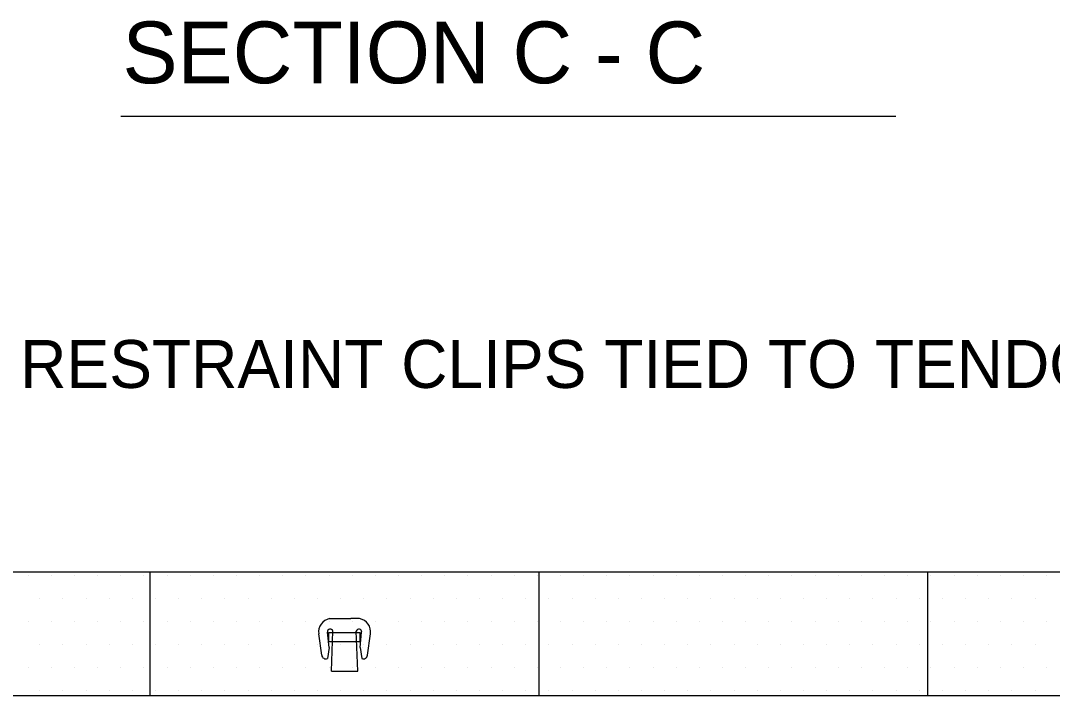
# Model space of a CAD drawing. Extents: x 638850 to 644908, y 297188 to 298900.
# Drawn here: x 641716.6 to 641776.8, y 297411.7 to 297451.1 of the extents above; entities that cross this region are included whole.
import ezdxf

# ---------------------------------------------------------------- set-up
doc = ezdxf.new("R2010")
doc.units = 0
for name, color, linetype in [('12', 7, 'Continuous'), ('3', 7, 'Continuous'), ('5', 7, 'Continuous'), ('7', 7, 'Continuous')]:
    doc.layers.add(name, color=color, linetype=linetype)

msp = doc.modelspace()

# ---------------------------------------------------------------- linework, layer by layer
at = {"layer": '12'}
for p, q in [((641717.032, 297418.735), (641717.032, 297418.735)), ((641718.382, 297418.735), (641718.382, 297418.735)), ((641719.732, 297418.735), (641719.732, 297418.735)), ((641721.082, 297418.735), (641721.082, 297418.735)), ((641722.432, 297418.735), (641722.432, 297418.735)), ((641723.782, 297418.735), (641723.782, 297418.735)), ((641725.132, 297418.735), (641725.132, 297418.735)), ((641726.482, 297418.735), (641726.482, 297418.735)), ((641727.832, 297418.735), (641727.832, 297418.735)), ((641729.182, 297418.735), (641729.182, 297418.735)), ((641730.532, 297418.735), (641730.532, 297418.735)), ((641731.882, 297418.735), (641731.882, 297418.735)), ((641733.232, 297418.735), (641733.232, 297418.735)), ((641734.582, 297418.735), (641734.582, 297418.735)), ((641735.932, 297418.735), (641735.932, 297418.735)), ((641737.282, 297418.735), (641737.282, 297418.735)), ((641738.632, 297418.735), (641738.632, 297418.735)), ((641739.982, 297418.735), (641739.982, 297418.735)), ((641741.332, 297418.735), (641741.332, 297418.735)), ((641742.682, 297418.735), (641742.682, 297418.735)), ((641744.032, 297418.735), (641744.032, 297418.735)), ((641745.382, 297418.735), (641745.382, 297418.735)), ((641746.732, 297418.735), (641746.732, 297418.735)), ((641748.082, 297418.735), (641748.082, 297418.735)), ((641749.432, 297418.735), (641749.432, 297418.735)), ((641750.782, 297418.735), (641750.782, 297418.735)), ((641752.132, 297418.735), (641752.132, 297418.735)), ((641753.482, 297418.735), (641753.482, 297418.735)), ((641754.832, 297418.735), (641754.832, 297418.735)), ((641756.182, 297418.735), (641756.182, 297418.735)), ((641757.532, 297418.735), (641757.532, 297418.735)), ((641758.882, 297418.735), (641758.882, 297418.735)), ((641760.232, 297418.735), (641760.232, 297418.735)), ((641761.582, 297418.735), (641761.582, 297418.735)), ((641762.932, 297418.735), (641762.932, 297418.735)), ((641764.282, 297418.735), (641764.282, 297418.735)), ((641765.632, 297418.735), (641765.632, 297418.735)), ((641766.982, 297418.735), (641766.982, 297418.735)), ((641768.332, 297418.735), (641768.332, 297418.735)), ((641769.682, 297418.735), (641769.682, 297418.735)), ((641771.032, 297418.735), (641771.032, 297418.735)), ((641772.382, 297418.735), (641772.382, 297418.735)), ((641773.732, 297418.735), (641773.732, 297418.735)), ((641775.082, 297418.735), (641775.082, 297418.735)), ((641776.432, 297418.735), (641776.432, 297418.735)), ((641717.706, 297417.385), (641717.706, 297417.385)), ((641719.058, 297417.385), (641719.058, 297417.385)), ((641720.406, 297417.385), (641720.406, 297417.385)), ((641721.758, 297417.385), (641721.758, 297417.385)), ((641723.106, 297417.385), (641723.106, 297417.385)), ((641724.458, 297417.385), (641724.458, 297417.385)), ((641725.806, 297417.385), (641725.806, 297417.385)), ((641727.158, 297417.385), (641727.158, 297417.385)), ((641728.506, 297417.385), (641728.506, 297417.385)), ((641729.858, 297417.385), (641729.858, 297417.385)), ((641731.206, 297417.385), (641731.206, 297417.385)), ((641732.558, 297417.385), (641732.558, 297417.385)), ((641733.906, 297417.385), (641733.906, 297417.385)), ((641735.258, 297417.385), (641735.258, 297417.385)), ((641736.606, 297417.385), (641736.606, 297417.385)), ((641737.958, 297417.385), (641737.958, 297417.385)), ((641739.306, 297417.385), (641739.306, 297417.385)), ((641740.658, 297417.385), (641740.658, 297417.385)), ((641742.006, 297417.385), (641742.006, 297417.385)), ((641743.358, 297417.385), (641743.358, 297417.385)), ((641744.706, 297417.385), (641744.706, 297417.385)), ((641746.058, 297417.385), (641746.058, 297417.385)), ((641747.406, 297417.385), (641747.406, 297417.385)), ((641748.758, 297417.385), (641748.758, 297417.385)), ((641750.106, 297417.385), (641750.106, 297417.385)), ((641751.458, 297417.385), (641751.458, 297417.385)), ((641752.806, 297417.385), (641752.806, 297417.385)), ((641754.158, 297417.385), (641754.158, 297417.385)), ((641755.506, 297417.385), (641755.506, 297417.385)), ((641756.858, 297417.385), (641756.858, 297417.385)), ((641758.206, 297417.385), (641758.206, 297417.385)), ((641759.558, 297417.385), (641759.558, 297417.385)), ((641760.906, 297417.385), (641760.906, 297417.385)), ((641762.258, 297417.385), (641762.258, 297417.385)), ((641763.606, 297417.385), (641763.606, 297417.385)), ((641764.958, 297417.385), (641764.958, 297417.385)), ((641766.306, 297417.385), (641766.306, 297417.385)), ((641767.658, 297417.385), (641767.658, 297417.385)), ((641769.006, 297417.385), (641769.006, 297417.385)), ((641770.358, 297417.385), (641770.358, 297417.385)), ((641771.706, 297417.385), (641771.706, 297417.385)), ((641773.058, 297417.385), (641773.058, 297417.385)), ((641774.406, 297417.385), (641774.406, 297417.385)), ((641775.758, 297417.385), (641775.758, 297417.385)), ((641717.032, 297416.035), (641717.032, 297416.035)), ((641718.382, 297416.035), (641718.382, 297416.035)), ((641719.732, 297416.035), (641719.732, 297416.035)), ((641721.082, 297416.035), (641721.082, 297416.035)), ((641722.432, 297416.035), (641722.432, 297416.035)), ((641723.782, 297416.035), (641723.782, 297416.035)), ((641725.132, 297416.035), (641725.132, 297416.035)), ((641726.482, 297416.035), (641726.482, 297416.035)), ((641727.832, 297416.035), (641727.832, 297416.035)), ((641729.182, 297416.035), (641729.182, 297416.035)), ((641730.532, 297416.035), (641730.532, 297416.035)), ((641731.882, 297416.035), (641731.882, 297416.035)), ((641733.232, 297416.035), (641733.232, 297416.035)), ((641734.582, 297416.035), (641734.582, 297416.035)), ((641735.932, 297416.035), (641735.932, 297416.035)), ((641737.282, 297416.035), (641737.282, 297416.035)), ((641738.632, 297416.035), (641738.632, 297416.035)), ((641739.982, 297416.035), (641739.982, 297416.035)), ((641741.332, 297416.035), (641741.332, 297416.035)), ((641742.682, 297416.035), (641742.682, 297416.035)), ((641744.032, 297416.035), (641744.032, 297416.035)), ((641745.382, 297416.035), (641745.382, 297416.035)), ((641746.732, 297416.035), (641746.732, 297416.035)), ((641748.082, 297416.035), (641748.082, 297416.035)), ((641749.432, 297416.035), (641749.432, 297416.035)), ((641750.782, 297416.035), (641750.782, 297416.035)), ((641752.132, 297416.035), (641752.132, 297416.035)), ((641753.482, 297416.035), (641753.482, 297416.035)), ((641754.832, 297416.035), (641754.832, 297416.035)), ((641756.182, 297416.035), (641756.182, 297416.035)), ((641757.532, 297416.035), (641757.532, 297416.035)), ((641758.882, 297416.035), (641758.882, 297416.035)), ((641760.232, 297416.035), (641760.232, 297416.035)), ((641761.582, 297416.035), (641761.582, 297416.035)), ((641762.932, 297416.035), (641762.932, 297416.035)), ((641764.282, 297416.035), (641764.282, 297416.035)), ((641765.632, 297416.035), (641765.632, 297416.035)), ((641766.982, 297416.035), (641766.982, 297416.035)), ((641768.332, 297416.035), (641768.332, 297416.035)), ((641769.682, 297416.035), (641769.682, 297416.035)), ((641771.032, 297416.035), (641771.032, 297416.035)), ((641772.382, 297416.035), (641772.382, 297416.035)), ((641773.732, 297416.035), (641773.732, 297416.035)), ((641775.082, 297416.035), (641775.082, 297416.035)), ((641776.432, 297416.035), (641776.432, 297416.035)), ((641717.706, 297414.685), (641717.706, 297414.685)), ((641719.058, 297414.685), (641719.058, 297414.685)), ((641720.406, 297414.685), (641720.406, 297414.685)), ((641721.758, 297414.685), (641721.758, 297414.685)), ((641723.106, 297414.685), (641723.106, 297414.685)), ((641724.458, 297414.685), (641724.458, 297414.685)), ((641725.806, 297414.685), (641725.806, 297414.685)), ((641727.158, 297414.685), (641727.158, 297414.685)), ((641728.506, 297414.685), (641728.506, 297414.685)), ((641729.858, 297414.685), (641729.858, 297414.685)), ((641731.206, 297414.685), (641731.206, 297414.685)), ((641732.558, 297414.685), (641732.558, 297414.685)), ((641733.906, 297414.685), (641733.906, 297414.685)), ((641735.258, 297414.685), (641735.258, 297414.685)), ((641736.606, 297414.685), (641736.606, 297414.685)), ((641737.958, 297414.685), (641737.958, 297414.685)), ((641739.306, 297414.685), (641739.306, 297414.685)), ((641740.658, 297414.685), (641740.658, 297414.685)), ((641742.006, 297414.685), (641742.006, 297414.685)), ((641743.358, 297414.685), (641743.358, 297414.685)), ((641744.706, 297414.685), (641744.706, 297414.685)), ((641746.058, 297414.685), (641746.058, 297414.685)), ((641747.406, 297414.685), (641747.406, 297414.685)), ((641748.758, 297414.685), (641748.758, 297414.685)), ((641750.106, 297414.685), (641750.106, 297414.685)), ((641751.458, 297414.685), (641751.458, 297414.685)), ((641752.806, 297414.685), (641752.806, 297414.685)), ((641754.158, 297414.685), (641754.158, 297414.685)), ((641755.506, 297414.685), (641755.506, 297414.685)), ((641756.858, 297414.685), (641756.858, 297414.685)), ((641758.206, 297414.685), (641758.206, 297414.685)), ((641759.558, 297414.685), (641759.558, 297414.685)), ((641760.906, 297414.685), (641760.906, 297414.685)), ((641762.258, 297414.685), (641762.258, 297414.685)), ((641763.606, 297414.685), (641763.606, 297414.685)), ((641764.958, 297414.685), (641764.958, 297414.685)), ((641766.306, 297414.685), (641766.306, 297414.685)), ((641767.658, 297414.685), (641767.658, 297414.685)), ((641769.006, 297414.685), (641769.006, 297414.685)), ((641770.358, 297414.685), (641770.358, 297414.685)), ((641771.706, 297414.685), (641771.706, 297414.685)), ((641773.058, 297414.685), (641773.058, 297414.685)), ((641774.406, 297414.685), (641774.406, 297414.685)), ((641775.758, 297414.685), (641775.758, 297414.685)), ((641717.032, 297413.335), (641717.032, 297413.335)), ((641718.382, 297413.335), (641718.382, 297413.335)), ((641719.732, 297413.335), (641719.732, 297413.335)), ((641721.082, 297413.335), (641721.082, 297413.335)), ((641722.432, 297413.335), (641722.432, 297413.335)), ((641723.782, 297413.335), (641723.782, 297413.335)), ((641725.132, 297413.335), (641725.132, 297413.335)), ((641726.482, 297413.335), (641726.482, 297413.335)), ((641727.832, 297413.335), (641727.832, 297413.335)), ((641729.182, 297413.335), (641729.182, 297413.335)), ((641730.532, 297413.335), (641730.532, 297413.335)), ((641731.882, 297413.335), (641731.882, 297413.335)), ((641733.232, 297413.335), (641733.232, 297413.335)), ((641734.582, 297413.335), (641734.582, 297413.335)), ((641735.932, 297413.335), (641735.932, 297413.335)), ((641737.282, 297413.335), (641737.282, 297413.335)), ((641738.632, 297413.335), (641738.632, 297413.335)), ((641739.982, 297413.335), (641739.982, 297413.335)), ((641741.332, 297413.335), (641741.332, 297413.335)), ((641742.682, 297413.335), (641742.682, 297413.335)), ((641744.032, 297413.335), (641744.032, 297413.335)), ((641745.382, 297413.335), (641745.382, 297413.335)), ((641746.732, 297413.335), (641746.732, 297413.335)), ((641748.082, 297413.335), (641748.082, 297413.335)), ((641749.432, 297413.335), (641749.432, 297413.335)), ((641750.782, 297413.335), (641750.782, 297413.335)), ((641752.132, 297413.335), (641752.132, 297413.335)), ((641753.482, 297413.335), (641753.482, 297413.335)), ((641754.832, 297413.335), (641754.832, 297413.335)), ((641756.182, 297413.335), (641756.182, 297413.335)), ((641757.532, 297413.335), (641757.532, 297413.335)), ((641758.882, 297413.335), (641758.882, 297413.335)), ((641760.232, 297413.335), (641760.232, 297413.335)), ((641761.582, 297413.335), (641761.582, 297413.335)), ((641762.932, 297413.335), (641762.932, 297413.335)), ((641764.282, 297413.335), (641764.282, 297413.335)), ((641765.632, 297413.335), (641765.632, 297413.335)), ((641766.982, 297413.335), (641766.982, 297413.335)), ((641768.332, 297413.335), (641768.332, 297413.335)), ((641769.682, 297413.335), (641769.682, 297413.335)), ((641771.032, 297413.335), (641771.032, 297413.335)), ((641772.382, 297413.335), (641772.382, 297413.335)), ((641773.732, 297413.335), (641773.732, 297413.335)), ((641775.082, 297413.335), (641775.082, 297413.335)), ((641776.432, 297413.335), (641776.432, 297413.335)), ((641717.706, 297411.985), (641717.706, 297411.985)), ((641719.058, 297411.985), (641719.058, 297411.985)), ((641720.406, 297411.985), (641720.406, 297411.985)), ((641721.758, 297411.985), (641721.758, 297411.985)), ((641723.106, 297411.985), (641723.106, 297411.985)), ((641724.458, 297411.985), (641724.458, 297411.985)), ((641725.806, 297411.985), (641725.806, 297411.985)), ((641727.158, 297411.985), (641727.158, 297411.985)), ((641728.506, 297411.985), (641728.506, 297411.985)), ((641729.858, 297411.985), (641729.858, 297411.985)), ((641731.206, 297411.985), (641731.206, 297411.985)), ((641732.558, 297411.985), (641732.558, 297411.985)), ((641733.906, 297411.985), (641733.906, 297411.985)), ((641735.258, 297411.985), (641735.258, 297411.985)), ((641736.606, 297411.985), (641736.606, 297411.985)), ((641737.958, 297411.985), (641737.958, 297411.985)), ((641739.306, 297411.985), (641739.306, 297411.985)), ((641740.658, 297411.985), (641740.658, 297411.985)), ((641742.006, 297411.985), (641742.006, 297411.985)), ((641743.358, 297411.985), (641743.358, 297411.985)), ((641744.706, 297411.985), (641744.706, 297411.985)), ((641746.058, 297411.985), (641746.058, 297411.985)), ((641747.406, 297411.985), (641747.406, 297411.985)), ((641748.758, 297411.985), (641748.758, 297411.985)), ((641750.106, 297411.985), (641750.106, 297411.985)), ((641751.458, 297411.985), (641751.458, 297411.985)), ((641752.806, 297411.985), (641752.806, 297411.985)), ((641754.158, 297411.985), (641754.158, 297411.985)), ((641755.506, 297411.985), (641755.506, 297411.985)), ((641756.858, 297411.985), (641756.858, 297411.985)), ((641758.206, 297411.985), (641758.206, 297411.985)), ((641759.558, 297411.985), (641759.558, 297411.985)), ((641760.906, 297411.985), (641760.906, 297411.985)), ((641762.258, 297411.985), (641762.258, 297411.985)), ((641763.606, 297411.985), (641763.606, 297411.985)), ((641764.958, 297411.985), (641764.958, 297411.985)), ((641766.306, 297411.985), (641766.306, 297411.985)), ((641767.658, 297411.985), (641767.658, 297411.985)), ((641769.006, 297411.985), (641769.006, 297411.985)), ((641770.358, 297411.985), (641770.358, 297411.985)), ((641771.706, 297411.985), (641771.706, 297411.985)), ((641773.058, 297411.985), (641773.058, 297411.985)), ((641774.406, 297411.985), (641774.406, 297411.985)), ((641775.758, 297411.985), (641775.758, 297411.985))]:
    msp.add_line(p, q, dxfattribs=at)
at = {"layer": '3'}
msp.add_line((641722.432, 297445.521), (641767.642, 297445.521), dxfattribs=at)
at = {"layer": '5'}
for p, q in [((641656.111, 297418.923), (641837.551, 297418.923)), ((641724.151, 297411.723), (641724.151, 297418.923)), ((641746.831, 297411.723), (641746.831, 297418.923)), ((641769.511, 297411.723), (641769.511, 297418.923)), ((641656.111, 297411.723), (641837.551, 297411.723))]:
    msp.add_line(p, q, dxfattribs=at)
at = {"layer": '7'}
for p, q in [((641734.61, 297416.199), (641735.124, 297416.199)), ((641735.124, 297416.199), (641735.849, 297416.199)), ((641736.363, 297416.199), (641735.849, 297416.199)), ((641734.152, 297414.06), (641733.977, 297415.307)), ((641734.584, 297414.523), (641734.491, 297415.41)), ((641734.722, 297413.138), (641734.804, 297415.477)), ((641736.251, 297413.138), (641736.169, 297415.477)), ((641736.389, 297414.523), (641736.482, 297415.41)), ((641736.821, 297414.06), (641736.996, 297415.307)), ((641734.584, 297414.523), (641734.484, 297413.875)), ((641736.389, 297414.523), (641736.489, 297413.875)), ((641734.722, 297413.138), (641736.251, 297413.138))]:
    msp.add_line(p, q, dxfattribs=at)
msp.add_lwpolyline([(641734.573, 297415.391), (641736.384, 297415.391), (641736.384, 297414.851), (641734.573, 297414.851)], close=True, dxfattribs=at)
for centre, radius, start, end in [((641734.763, 297415.419), 0.795, 101.12312, 188.00088), ((641736.21, 297415.419), 0.795, 351.99912, 78.87688), ((641734.649, 297415.434), 0.161, 15.90134, 188.20491), ((641736.324, 297415.434), 0.161, 351.79509, 164.09866), ((641734.388, 297414.094), 0.239, 188.00002, 293.85999), ((641736.585, 297414.094), 0.239, 246.14, 351.99998), ((641736.511, 297414.32), 0.21, 83.80646, 85.56349)]:
    msp.add_arc(centre, radius, start, end, dxfattribs=at)

# ---------------------------------------------------------------- texts
at = {"layer": '3'}
for s, height, p in [('SECTION C - C', 3.60225, (641722.533, 297447.438)), ('RESTRAINT CLIPS TIED TO TENDONS WITH MOORE HITCH', 2.79547, (641716.566, 297429.661))]:
    msp.add_text(s, height=height, dxfattribs=at).set_placement(p)

doc.saveas('drawing.dxf')
